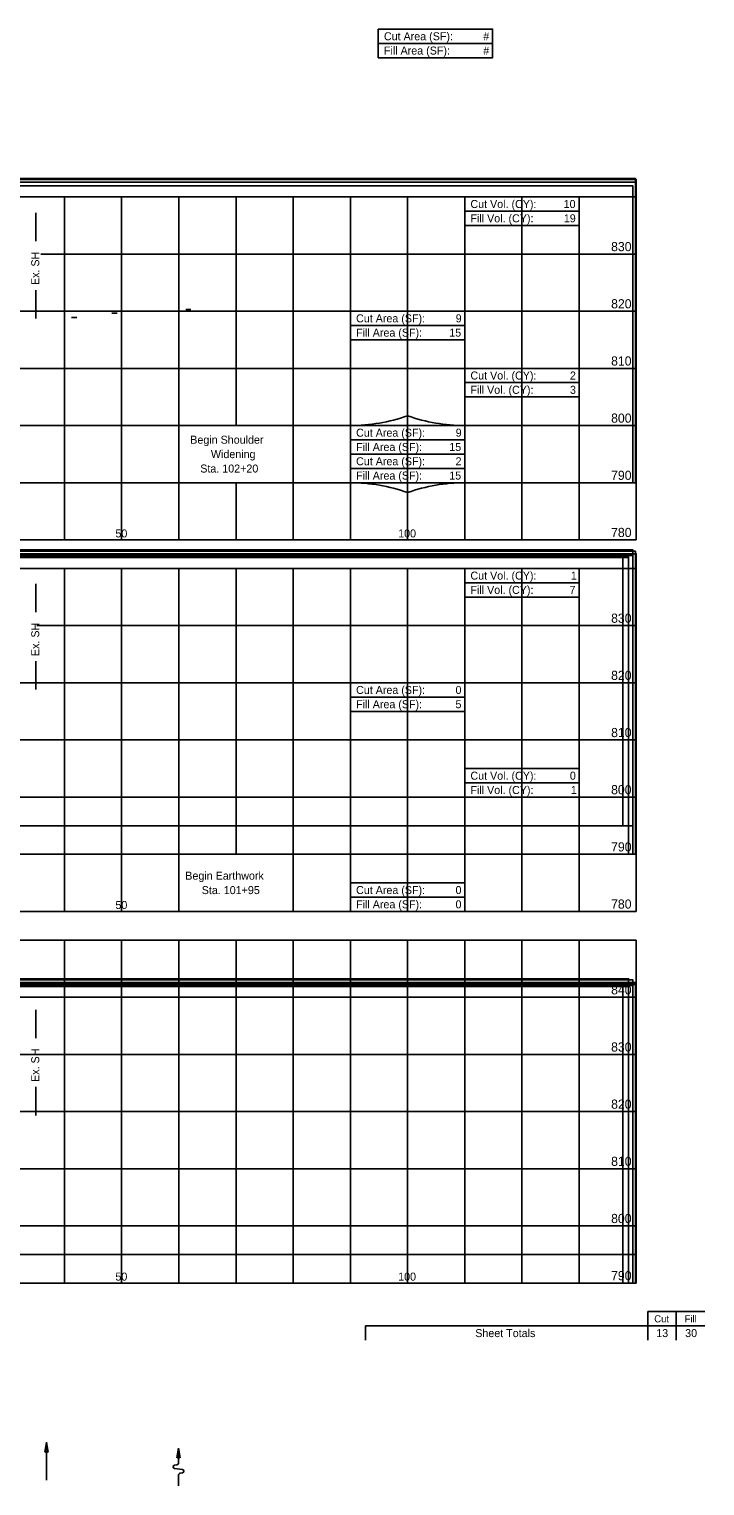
# Model space of a CAD drawing. Extents: x -475 to 76, y 0 to 417.
# Drawn here: x -455.22 to -443.41, y 364.12 to 389.6 of the extents above; entities that cross this region are included whole.
import ezdxf

# ---------------------------------------------------------------- set-up
doc = ezdxf.new("R2010")
doc.units = 0
for name, color, linetype in [('_CIVIL_CONSTRUCTION', 7, 'Continuous'), ('Default', 7, 'Continuous'), ('RW_P_Esmt_TMP', 7, 'Continuous'), ('RW_X_Text', 7, 'Continuous'), ('SC_Scratch1', 7, 'Continuous'), ('SC_Scratch10', 7, 'Continuous'), ('SH_Masking', 7, 'Continuous'), ('SV_P_Mon_Cells_Set', 7, 'Continuous'), ('SV_X_Random_Point', 7, 'Continuous')]:
    doc.layers.add(name, color=color, linetype=linetype)

msp = doc.modelspace()

# ---------------------------------------------------------------- linework, layer by layer
at = {"layer": '_CIVIL_CONSTRUCTION'}
for points in [[(-472.658, 381.665), (-444.665, 381.665), (-444.665, 386.856), (-472.658, 386.856)], [(-472.658, 381.665), (-444.665, 381.665), (-444.665, 386.856), (-472.658, 386.856)], [(-472.619, 381.665), (-444.621, 381.665), (-444.621, 386.989), (-472.619, 386.989)], [(-472.619, 381.665), (-444.621, 381.665), (-444.621, 386.989), (-472.619, 386.989)], [(-472.619, 381.665), (-444.621, 381.665), (-444.621, 386.923), (-472.619, 386.923)], [(-472.619, 381.665), (-444.621, 381.665), (-444.621, 386.923), (-472.619, 386.923)], [(-472.606, 381.665), (-444.606, 381.665), (-444.606, 386.968), (-472.606, 386.968)], [(-472.658, 375.165), (-444.665, 375.165), (-444.665, 380.489), (-472.658, 380.489)], [(-472.658, 375.165), (-444.665, 375.165), (-444.665, 380.489), (-472.658, 380.489)], [(-472.619, 375.165), (-444.621, 375.165), (-444.621, 380.468), (-472.619, 380.468)], [(-472.619, 375.165), (-444.621, 375.165), (-444.621, 380.468), (-472.619, 380.468)], [(-472.815, 375.665), (-444.842, 375.665), (-444.842, 380.364), (-472.815, 380.364)], [(-472.815, 375.665), (-444.842, 375.665), (-444.842, 380.364), (-472.815, 380.364)], [(-472.815, 375.665), (-444.842, 375.665), (-444.842, 380.354), (-472.815, 380.354)], [(-472.815, 375.665), (-444.842, 375.665), (-444.842, 380.354), (-472.815, 380.354)], [(-472.724, 375.665), (-444.739, 375.665), (-444.739, 380.371), (-472.724, 380.371)], [(-472.724, 375.665), (-444.739, 375.665), (-444.739, 380.371), (-472.724, 380.371)], [(-472.724, 375.165), (-444.739, 375.165), (-444.739, 380.356), (-472.724, 380.356)], [(-472.724, 375.165), (-444.739, 375.165), (-444.739, 380.356), (-472.724, 380.356)], [(-472.658, 375.665), (-444.665, 375.665), (-444.665, 380.389), (-472.658, 380.389)], [(-472.658, 375.665), (-444.665, 375.665), (-444.665, 380.389), (-472.658, 380.389)], [(-472.606, 375.165), (-444.606, 375.165), (-444.606, 380.423), (-472.606, 380.423)], [(-472.815, 367.665), (-444.842, 367.665), (-444.842, 372.856), (-472.815, 372.856)], [(-472.815, 367.665), (-444.842, 367.665), (-444.842, 372.856), (-472.815, 372.856)], [(-472.724, 367.665), (-444.739, 367.665), (-444.739, 372.989), (-472.724, 372.989)], [(-472.724, 367.665), (-444.739, 367.665), (-444.739, 372.989), (-472.724, 372.989)], [(-472.724, 368.165), (-444.739, 368.165), (-444.739, 372.854), (-472.724, 372.854)], [(-472.724, 368.165), (-444.739, 368.165), (-444.739, 372.854), (-472.724, 372.854)], [(-472.658, 367.665), (-444.665, 367.665), (-444.665, 372.968), (-472.658, 372.968)], [(-472.658, 367.665), (-444.665, 367.665), (-444.665, 372.968), (-472.658, 372.968)], [(-472.658, 368.165), (-444.665, 368.165), (-444.665, 372.871), (-472.658, 372.871)], [(-472.658, 368.165), (-444.665, 368.165), (-444.665, 372.871), (-472.658, 372.871)], [(-472.619, 367.665), (-444.621, 367.665), (-444.621, 372.923), (-472.619, 372.923)], [(-472.619, 367.665), (-444.621, 367.665), (-444.621, 372.923), (-472.619, 372.923)], [(-472.619, 368.165), (-444.621, 368.165), (-444.621, 372.889), (-472.619, 372.889)], [(-472.619, 368.165), (-444.621, 368.165), (-444.621, 372.889), (-472.619, 372.889)], [(-472.606, 368.165), (-444.606, 368.165), (-444.606, 372.909), (-472.606, 372.909)], [(-472.606, 368.165), (-444.606, 368.165), (-444.606, 372.909), (-472.606, 372.909)]]:
    msp.add_lwpolyline(points, close=True, dxfattribs=at)
at = {"layer": 'Default'}
for p, q in [((-444.406, 366.665), (-444.406, 367.165)), ((-443.906, 366.665), (-443.906, 367.165)), ((-449.342, 366.665), (-449.342, 366.915)), ((-454.951, 364.708), (-454.922, 364.881)), ((-454.951, 364.708), (-454.951, 364.708)), ((-454.922, 364.881), (-454.893, 364.708)), ((-454.922, 364.219), (-454.922, 364.881)), ((-454.893, 364.708), (-454.893, 364.708)), ((-452.641, 364.607), (-452.612, 364.78)), ((-452.612, 364.78), (-452.583, 364.606)), ((-452.612, 364.523), (-452.612, 364.78)), ((-452.682, 364.479), (-452.642, 364.487)), ((-452.542, 364.403), (-452.681, 364.424)), ((-452.641, 364.607), (-452.641, 364.607)), ((-452.583, 364.606), (-452.583, 364.606)), ((-452.612, 364.118), (-452.612, 364.303)), ((-452.581, 364.34), (-452.541, 364.347))]:
    msp.add_line(p, q, dxfattribs=at)
for centre, radius, start, end in [((-454.922, 364.664), 0.0527, 56.178, 122.8588), ((-452.677, 364.451), 0.0281, 100.6197, 261.4692), ((-452.649, 364.523), 0.0375, 280.6197, 360), ((-452.612, 364.562), 0.0527, 56.178, 122.8588), ((-452.546, 364.375), 0.0281, 280.6197, 81.4692), ((-452.574, 364.303), 0.0375, 100.6197, 180)]:
    msp.add_arc(centre, radius, start, end, dxfattribs=at)
at = {"layer": 'RW_P_Esmt_TMP'}
for p, q in [((-472.606, 386.665), (-444.606, 386.665)), ((-444.606, 380.665), (-444.606, 386.665)), ((-472.606, 380.665), (-444.606, 380.665)), ((-472.606, 380.165), (-444.606, 380.165)), ((-444.606, 374.165), (-444.606, 380.165)), ((-472.606, 374.165), (-444.606, 374.165)), ((-472.606, 373.665), (-444.606, 373.665)), ((-444.606, 367.665), (-444.606, 373.665)), ((-472.606, 367.665), (-444.606, 367.665))]:
    msp.add_line(p, q, dxfattribs=at)
at = {"layer": 'RW_X_Text'}
for p, q in [((-455.106, 385.888), (-455.106, 386.384)), ((-455.106, 384.539), (-455.106, 385.035)), ((-455.106, 379.398), (-455.106, 379.895)), ((-455.106, 378.049), (-455.106, 378.545)), ((-455.106, 371.948), (-455.106, 372.445)), ((-455.106, 370.599), (-455.106, 371.096))]:
    msp.add_line(p, q, dxfattribs=at)
at = {"layer": 'SC_Scratch1'}
for p, q in [((-449.119, 389.599), (-447.119, 389.599)), ((-449.119, 389.599), (-449.119, 389.099)), ((-447.119, 389.599), (-447.119, 389.099)), ((-449.119, 389.349), (-447.119, 389.349)), ((-449.119, 389.099), (-447.119, 389.099)), ((-447.606, 386.665), (-445.606, 386.665)), ((-447.606, 386.665), (-447.606, 386.165)), ((-445.606, 386.665), (-445.606, 386.165)), ((-447.606, 386.415), (-445.606, 386.415)), ((-447.606, 386.165), (-445.606, 386.165)), ((-449.606, 384.665), (-447.606, 384.665)), ((-449.606, 384.665), (-449.606, 384.165)), ((-447.606, 384.665), (-447.606, 384.165)), ((-449.606, 384.415), (-447.606, 384.415)), ((-449.606, 384.165), (-447.606, 384.165)), ((-447.606, 383.665), (-445.606, 383.665)), ((-447.606, 383.665), (-447.606, 383.165)), ((-445.606, 383.665), (-445.606, 383.165)), ((-447.606, 383.415), (-445.606, 383.415)), ((-447.606, 383.165), (-445.606, 383.165)), ((-449.606, 382.665), (-447.606, 382.665)), ((-449.606, 382.665), (-449.606, 382.165)), ((-447.606, 382.665), (-449.606, 382.665)), ((-447.606, 382.665), (-447.606, 382.165)), ((-449.606, 382.415), (-447.606, 382.415)), ((-449.606, 382.165), (-447.606, 382.165)), ((-449.606, 382.165), (-447.606, 382.165)), ((-449.606, 382.165), (-449.606, 381.665)), ((-447.606, 382.165), (-447.606, 381.665)), ((-449.606, 381.915), (-447.606, 381.915)), ((-449.606, 381.665), (-447.606, 381.665)), ((-447.606, 381.665), (-449.606, 381.665)), ((-447.606, 380.165), (-445.606, 380.165)), ((-447.606, 380.165), (-447.606, 379.665)), ((-445.606, 380.165), (-445.606, 379.665)), ((-447.606, 379.915), (-445.606, 379.915)), ((-447.606, 379.665), (-445.606, 379.665)), ((-449.606, 378.165), (-447.606, 378.165)), ((-449.606, 378.165), (-449.606, 377.665)), ((-447.606, 378.165), (-447.606, 377.665)), ((-449.606, 377.915), (-447.606, 377.915)), ((-449.606, 377.665), (-447.606, 377.665)), ((-447.606, 376.665), (-445.606, 376.665)), ((-447.606, 376.665), (-447.606, 376.165)), ((-445.606, 376.665), (-445.606, 376.165)), ((-447.606, 376.415), (-445.606, 376.415)), ((-447.606, 376.165), (-445.606, 376.165)), ((-449.606, 374.665), (-447.606, 374.665)), ((-449.606, 374.665), (-449.606, 374.165)), ((-447.606, 374.665), (-447.606, 374.165)), ((-449.606, 374.415), (-447.606, 374.415)), ((-449.606, 374.165), (-447.606, 374.165)), ((-444.406, 367.165), (-443.406, 367.165)), ((-449.342, 366.915), (-443.406, 366.915))]:
    msp.add_line(p, q, dxfattribs=at)
for centre, start, end in [((-449.606, 385.665), 270, 289.4712), ((-447.606, 385.665), 250.5288, 270), ((-449.606, 378.665), 70.5288, 90), ((-447.606, 378.665), 90, 109.4712)]:
    msp.add_arc(centre, 3, start, end, dxfattribs=at)
at = {"layer": 'SH_Masking'}
for points in [[(-449.119, 389.599), (-447.119, 389.599), (-447.119, 389.099), (-449.119, 389.099)], [(-447.606, 386.665), (-445.606, 386.665), (-445.606, 386.165), (-447.606, 386.165)], [(-449.606, 384.665), (-447.606, 384.665), (-447.606, 384.165), (-449.606, 384.165)], [(-447.606, 383.665), (-445.606, 383.665), (-445.606, 383.165), (-447.606, 383.165)], [(-449.606, 382.665), (-447.606, 382.665), (-447.606, 382.165), (-449.606, 382.165)], [(-449.606, 382.165), (-447.606, 382.165), (-447.606, 381.665), (-449.606, 381.665)], [(-447.606, 380.165), (-445.606, 380.165), (-445.606, 379.665), (-447.606, 379.665)], [(-449.606, 378.165), (-447.606, 378.165), (-447.606, 377.665), (-449.606, 377.665)], [(-447.606, 376.665), (-445.606, 376.665), (-445.606, 376.165), (-447.606, 376.165)], [(-449.606, 374.665), (-447.606, 374.665), (-447.606, 374.165), (-449.606, 374.165)]]:
    msp.add_lwpolyline(points, close=True, dxfattribs=at)
at = {"layer": 'SV_P_Mon_Cells_Set'}
for p, q in [((-454.606, 380.665), (-454.606, 386.665)), ((-453.606, 380.665), (-453.606, 386.665)), ((-452.606, 380.665), (-452.606, 386.665)), ((-451.606, 382.665), (-451.606, 386.665)), ((-450.606, 380.665), (-450.606, 386.665)), ((-449.606, 380.665), (-449.606, 386.665)), ((-448.606, 380.665), (-448.606, 386.665)), ((-447.606, 380.665), (-447.606, 386.665)), ((-446.606, 380.665), (-446.606, 386.665)), ((-445.606, 380.665), (-445.606, 386.665)), ((-455.022, 385.665), (-444.606, 385.665)), ((-455.555, 384.665), (-444.606, 384.665)), ((-456.405, 383.665), (-444.606, 383.665)), ((-472.606, 382.665), (-444.606, 382.665)), ((-472.606, 381.665), (-444.606, 381.665)), ((-451.606, 380.665), (-451.606, 381.665)), ((-454.606, 374.165), (-454.606, 380.165)), ((-453.606, 374.165), (-453.606, 380.165)), ((-452.606, 374.165), (-452.606, 380.165)), ((-451.606, 375.165), (-451.606, 380.165)), ((-450.606, 374.165), (-450.606, 380.165)), ((-449.606, 374.165), (-449.606, 380.165)), ((-448.606, 374.165), (-448.606, 380.165)), ((-447.606, 374.165), (-447.606, 380.165)), ((-446.606, 374.165), (-446.606, 380.165)), ((-445.606, 374.165), (-445.606, 380.165)), ((-455.091, 379.165), (-444.606, 379.165)), ((-456.111, 378.165), (-444.606, 378.165)), ((-472.606, 377.165), (-444.606, 377.165)), ((-472.606, 376.165), (-444.606, 376.165)), ((-472.606, 375.165), (-444.606, 375.165)), ((-454.606, 367.665), (-454.606, 373.665)), ((-453.606, 367.665), (-453.606, 373.665)), ((-452.606, 367.665), (-452.606, 373.665)), ((-451.606, 367.665), (-451.606, 373.665)), ((-450.606, 367.665), (-450.606, 373.665)), ((-449.606, 367.665), (-449.606, 373.665)), ((-448.606, 367.665), (-448.606, 373.665)), ((-447.606, 367.665), (-447.606, 373.665)), ((-446.606, 367.665), (-446.606, 373.665)), ((-445.606, 367.665), (-445.606, 373.665)), ((-472.606, 372.665), (-444.606, 372.665)), ((-455.428, 371.665), (-444.606, 371.665)), ((-472.606, 370.665), (-444.606, 370.665)), ((-472.606, 369.665), (-444.606, 369.665)), ((-472.606, 368.665), (-444.606, 368.665))]:
    msp.add_line(p, q, dxfattribs=at)
at = {"layer": 'SV_X_Random_Point'}
for p, q in [((-454.392, 384.555), (-454.482, 384.555)), ((-454.423, 384.555), (-454.452, 384.555)), ((-453.686, 384.631), (-453.776, 384.631)), ((-453.716, 384.631), (-453.746, 384.631)), ((-452.394, 384.695), (-452.484, 384.695)), ((-452.424, 384.695), (-452.454, 384.695))]:
    msp.add_line(p, q, dxfattribs=at)

# ---------------------------------------------------------------- texts
at = {"layer": 'Default'}
for s, height, p in [('Cut', 0.125, (-444.292, 366.977)), ('Fill', 0.125, (-443.762, 366.977)), ('Sheet Totals', 0.14, (-447.422, 366.72)), ('13', 0.14, (-444.256, 366.72)), ('30', 0.14, (-443.751, 366.72))]:
    msp.add_text(s, height=height, dxfattribs=at).set_placement(p)
at = {"layer": 'RW_X_Text'}
for p in [(-455.047, 385.123), (-455.047, 378.633), (-455.047, 371.184)]:
    msp.add_text('Ex. SH', height=0.14, rotation=90, dxfattribs=at).set_placement(p)
at = {"layer": 'SC_Scratch10'}
for s, height, p in [('Cut Area (SF):', 0.14, (-449.019, 389.404)), ('#', 0.14, (-447.282, 389.404)), ('Fill Area (SF):', 0.14, (-449.019, 389.154)), ('#', 0.14, (-447.282, 389.154)), ('Cut Vol. (CY):', 0.14, (-447.506, 386.47)), ('10', 0.14, (-445.876, 386.47)), ('Fill Vol. (CY):', 0.14, (-447.506, 386.22)), ('19', 0.14, (-445.873, 386.22)), ('830', 0.16, (-445.046, 385.715)), ('820', 0.16, (-445.046, 384.715)), ('Cut Area (SF):', 0.14, (-449.506, 384.47)), ('9', 0.14, (-447.764, 384.47)), ('Fill Area (SF):', 0.14, (-449.506, 384.22)), ('15', 0.14, (-447.877, 384.22)), ('810', 0.16, (-445.046, 383.715)), ('Cut Vol. (CY):', 0.14, (-447.506, 383.47)), ('2', 0.14, (-445.766, 383.47)), ('Fill Vol. (CY):', 0.14, (-447.506, 383.22)), ('3', 0.14, (-445.765, 383.22)), ('800', 0.16, (-445.046, 382.715)), ('Begin Shoulder', 0.14, (-452.406, 382.347)), ('Cut Area (SF):', 0.14, (-449.506, 382.47)), ('9', 0.14, (-447.764, 382.47)), ('Widening', 0.14, (-452.045, 382.095)), ('Fill Area (SF):', 0.14, (-449.506, 382.22)), ('15', 0.14, (-447.877, 382.22)), ('Sta. 102+20', 0.14, (-452.231, 381.843)), ('Cut Area (SF):', 0.14, (-449.506, 381.97)), ('2', 0.14, (-447.766, 381.97)), ('Fill Area (SF):', 0.14, (-449.506, 381.72)), ('15', 0.14, (-447.877, 381.72)), ('790', 0.16, (-445.046, 381.715)), ('50', 0.14, (-453.715, 380.708)), ('100', 0.14, (-448.77, 380.708)), ('780', 0.16, (-445.046, 380.715)), ('Cut Vol. (CY):', 0.14, (-447.506, 379.97)), ('1', 0.14, (-445.75, 379.97)), ('Fill Vol. (CY):', 0.14, (-447.506, 379.72)), ('7', 0.14, (-445.773, 379.72)), ('830', 0.16, (-445.046, 379.215)), ('820', 0.16, (-445.046, 378.215)), ('Cut Area (SF):', 0.14, (-449.506, 377.97)), ('0', 0.14, (-447.767, 377.97)), ('Fill Area (SF):', 0.14, (-449.506, 377.72)), ('5', 0.14, (-447.768, 377.72)), ('810', 0.16, (-445.046, 377.215)), ('Cut Vol. (CY):', 0.14, (-447.506, 376.47)), ('0', 0.14, (-445.767, 376.47)), ('Fill Vol. (CY):', 0.14, (-447.506, 376.22)), ('1', 0.14, (-445.75, 376.22)), ('800', 0.16, (-445.046, 376.215)), ('790', 0.16, (-445.046, 375.215)), ('Begin Earthwork', 0.14, (-452.493, 374.721)), ('Sta. 101+95', 0.14, (-452.205, 374.469)), ('Cut Area (SF):', 0.14, (-449.506, 374.47)), ('0', 0.14, (-447.767, 374.47)), ('50', 0.14, (-453.715, 374.208)), ('Fill Area (SF):', 0.14, (-449.506, 374.22)), ('0', 0.14, (-447.767, 374.22)), ('780', 0.16, (-445.046, 374.215)), ('840', 0.16, (-445.046, 372.715)), ('830', 0.16, (-445.046, 371.715)), ('820', 0.16, (-445.046, 370.715)), ('810', 0.16, (-445.046, 369.715)), ('800', 0.16, (-445.046, 368.715)), ('50', 0.14, (-453.715, 367.708)), ('100', 0.14, (-448.77, 367.708)), ('790', 0.16, (-445.046, 367.715))]:
    msp.add_text(s, height=height, dxfattribs=at).set_placement(p)

doc.saveas('drawing.dxf')
